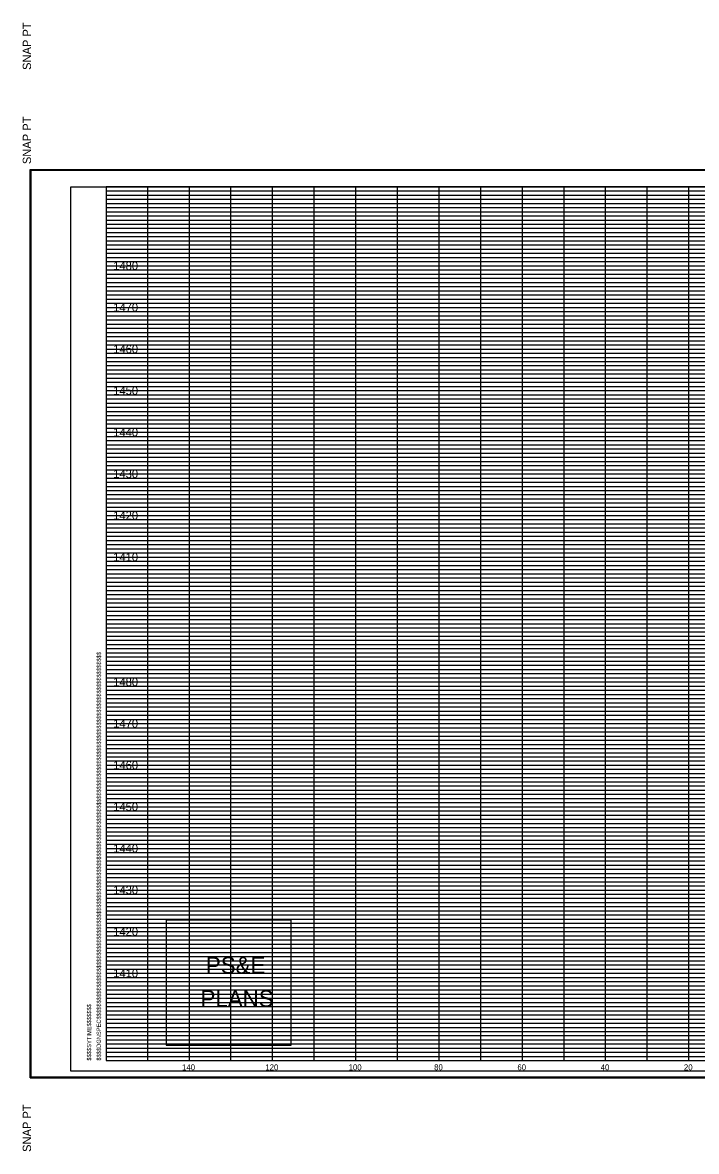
# Model space of a CAD drawing. Extents: x 980 to 2064, y 978 to 2267.
# Drawn here: x 979.9 to 1141.8, y 978.2 to 1249.4 of the extents above; entities that cross this region are included whole.
import ezdxf

# ---------------------------------------------------------------- set-up
doc = ezdxf.new("R2010")
doc.units = 0
for name, color, linetype in [('Default', 7, 'Continuous'), ('DESIGN - SHEET - Corner Text', 7, 'Continuous'), ('DESIGN - SHEET - Light Grid', 7, 'Continuous'), ('DESIGN - SHEET - Linework', 7, 'Continuous'), ('DESIGN - SHEET - Plot Shape', 7, 'Continuous')]:
    doc.layers.add(name, color=color, linetype=linetype)

# ---------------------------------------------------------------- blocks, each defined once
blk = doc.blocks.new('XSTSHT')
at = {"layer": 'DESIGN - SHEET - Light Grid'}
for p, q in [((0, 20.9), (8, 20.9)), ((8, 20.9), (16, 20.9)), ((0, 20.8), (8, 20.8)), ((0, 20.7), (8, 20.7)), ((8, 20.8), (16, 20.8)), ((8, 20.7), (16, 20.7)), ((0, 20.6), (8, 20.6)), ((0, 20.5), (8, 20.5)), ((0, 20.4), (8, 20.4)), ((8, 20.6), (16, 20.6)), ((8, 20.5), (16, 20.5)), ((8, 20.4), (16, 20.4)), ((0, 20.3), (8, 20.3)), ((0, 20.2), (8, 20.2)), ((0, 20.1), (8, 20.1)), ((8, 20.3), (16, 20.3)), ((8, 20.2), (16, 20.2)), ((8, 20.1), (16, 20.1)), ((0, 19.9), (8, 19.9)), ((8, 19.9), (16, 19.9)), ((0, 19.8), (8, 19.8)), ((0, 19.7), (8, 19.7)), ((0, 19.6), (8, 19.6)), ((8, 19.8), (16, 19.8)), ((8, 19.7), (16, 19.7)), ((8, 19.6), (16, 19.6)), ((0, 19.5), (8, 19.5)), ((0, 19.4), (8, 19.4)), ((0, 19.3), (8, 19.3)), ((8, 19.5), (16, 19.5)), ((8, 19.4), (16, 19.4)), ((8, 19.3), (16, 19.3)), ((0, 19.2), (8, 19.2)), ((0, 19.1), (8, 19.1)), ((8, 19.2), (16, 19.2)), ((8, 19.1), (16, 19.1)), ((0, 18.9), (8, 18.9)), ((0, 18.8), (8, 18.8)), ((8, 18.9), (16, 18.9)), ((8, 18.8), (16, 18.8)), ((0, 18.7), (8, 18.7)), ((0, 18.6), (8, 18.6)), ((0, 18.5), (8, 18.5)), ((8, 18.7), (16, 18.7)), ((8, 18.6), (16, 18.6)), ((8, 18.5), (16, 18.5)), ((0, 18.4), (8, 18.4)), ((0, 18.3), (8, 18.3)), ((0, 18.2), (8, 18.2)), ((8, 18.4), (16, 18.4)), ((8, 18.3), (16, 18.3)), ((8, 18.2), (16, 18.2)), ((0, 18.1), (8, 18.1)), ((8, 18.1), (16, 18.1)), ((0, 17.9), (8, 17.9)), ((0, 17.8), (8, 17.8)), ((0, 17.7), (8, 17.7)), ((8, 17.9), (16, 17.9)), ((8, 17.8), (16, 17.8)), ((8, 17.7), (16, 17.7)), ((0, 17.6), (8, 17.6)), ((0, 17.5), (8, 17.5)), ((0, 17.4), (8, 17.4)), ((8, 17.6), (16, 17.6)), ((8, 17.5), (16, 17.5)), ((8, 17.4), (16, 17.4)), ((0, 17.3), (8, 17.3)), ((0, 17.2), (8, 17.2)), ((0, 17.1), (8, 17.1)), ((8, 17.3), (16, 17.3)), ((8, 17.2), (16, 17.2)), ((8, 17.1), (16, 17.1)), ((0, 16.9), (8, 16.9)), ((8, 16.9), (16, 16.9)), ((0, 16.8), (8, 16.8)), ((0, 16.7), (8, 16.7)), ((0, 16.6), (8, 16.6)), ((8, 16.8), (16, 16.8)), ((8, 16.7), (16, 16.7)), ((8, 16.6), (16, 16.6)), ((0, 16.5), (8, 16.5)), ((0, 16.4), (8, 16.4)), ((0, 16.3), (8, 16.3)), ((8, 16.5), (16, 16.5)), ((8, 16.4), (16, 16.4)), ((8, 16.3), (16, 16.3)), ((0, 16.2), (8, 16.2)), ((0, 16.1), (8, 16.1)), ((8, 16.2), (16, 16.2)), ((8, 16.1), (16, 16.1)), ((0, 15.9), (8, 15.9)), ((0, 15.8), (8, 15.8)), ((8, 15.9), (16, 15.9)), ((8, 15.8), (16, 15.8)), ((0, 15.7), (8, 15.7)), ((0, 15.6), (8, 15.6)), ((0, 15.5), (8, 15.5)), ((8, 15.7), (16, 15.7)), ((8, 15.6), (16, 15.6)), ((8, 15.5), (16, 15.5)), ((0, 15.4), (8, 15.4)), ((0, 15.3), (8, 15.3)), ((0, 15.2), (8, 15.2)), ((8, 15.4), (16, 15.4)), ((8, 15.3), (16, 15.3)), ((8, 15.2), (16, 15.2)), ((0, 15.1), (8, 15.1)), ((8, 15.1), (16, 15.1)), ((0, 14.9), (8, 14.9)), ((0, 14.8), (8, 14.8)), ((0, 14.7), (8, 14.7)), ((8, 14.9), (16, 14.9)), ((8, 14.8), (16, 14.8)), ((8, 14.7), (16, 14.7)), ((0, 14.6), (8, 14.6)), ((0, 14.5), (8, 14.5)), ((0, 14.4), (8, 14.4)), ((8, 14.6), (16, 14.6)), ((8, 14.5), (16, 14.5)), ((8, 14.4), (16, 14.4)), ((0, 14.3), (8, 14.3)), ((0, 14.2), (8, 14.2)), ((8, 14.3), (16, 14.3)), ((8, 14.2), (16, 14.2)), ((0, 14.1), (8, 14.1)), ((0, 13.9), (8, 13.9)), ((8, 14.1), (16, 14.1)), ((8, 13.9), (16, 13.9)), ((0, 13.8), (8, 13.8)), ((0, 13.7), (8, 13.7)), ((0, 13.6), (8, 13.6)), ((8, 13.8), (16, 13.8)), ((8, 13.7), (16, 13.7)), ((8, 13.6), (16, 13.6)), ((0, 13.5), (8, 13.5)), ((0, 13.4), (8, 13.4)), ((0, 13.3), (8, 13.3)), ((8, 13.5), (16, 13.5)), ((8, 13.4), (16, 13.4)), ((8, 13.3), (16, 13.3)), ((0, 13.2), (8, 13.2)), ((0, 13.1), (8, 13.1)), ((8, 13.2), (16, 13.2)), ((8, 13.1), (16, 13.1)), ((0, 12.9), (8, 12.9)), ((0, 12.8), (8, 12.8)), ((8, 12.9), (16, 12.9)), ((8, 12.8), (16, 12.8)), ((0, 12.7), (8, 12.7)), ((0, 12.6), (8, 12.6)), ((0, 12.5), (8, 12.5)), ((8, 12.7), (16, 12.7)), ((8, 12.6), (16, 12.6)), ((8, 12.5), (16, 12.5)), ((0, 12.4), (8, 12.4)), ((0, 12.3), (8, 12.3)), ((8, 12.4), (16, 12.4)), ((8, 12.3), (16, 12.3)), ((0, 12.2), (8, 12.2)), ((0, 12.1), (8, 12.1)), ((8, 12.2), (16, 12.2)), ((8, 12.1), (16, 12.1)), ((0, 11.9), (8, 11.9)), ((0, 11.8), (8, 11.8)), ((0, 11.7), (8, 11.7)), ((8, 11.9), (16, 11.9)), ((8, 11.8), (16, 11.8)), ((8, 11.7), (16, 11.7)), ((0, 11.6), (8, 11.6)), ((0, 11.5), (8, 11.5)), ((0, 11.4), (8, 11.4)), ((8, 11.6), (16, 11.6)), ((8, 11.5), (16, 11.5)), ((8, 11.4), (16, 11.4)), ((0, 11.3), (8, 11.3)), ((0, 11.2), (8, 11.2)), ((8, 11.3), (16, 11.3)), ((8, 11.2), (16, 11.2)), ((0, 11.1), (8, 11.1)), ((0, 10.9), (8, 10.9)), ((8, 11.1), (16, 11.1)), ((8, 10.9), (16, 10.9)), ((0, 10.8), (8, 10.8)), ((0, 10.7), (8, 10.7)), ((0, 10.6), (8, 10.6)), ((8, 10.8), (16, 10.8)), ((8, 10.7), (16, 10.7)), ((8, 10.6), (16, 10.6)), ((0, 10.5), (8, 10.5)), ((0, 10.4), (8, 10.4)), ((8, 10.5), (16, 10.5)), ((8, 10.4), (16, 10.4)), ((0, 10.3), (8, 10.3)), ((0, 10.2), (8, 10.2)), ((0, 10.1), (8, 10.1)), ((8, 10.3), (16, 10.3)), ((8, 10.2), (16, 10.2)), ((8, 10.1), (16, 10.1)), ((0, 9.9), (8, 9.9)), ((0, 9.8), (8, 9.8)), ((8, 9.9), (16, 9.9)), ((8, 9.8), (16, 9.8)), ((0, 9.7), (8, 9.7)), ((0, 9.6), (8, 9.6)), ((0, 9.5), (8, 9.5)), ((8, 9.7), (16, 9.7)), ((8, 9.6), (16, 9.6)), ((8, 9.5), (16, 9.5)), ((0, 9.4), (8, 9.4)), ((0, 9.3), (8, 9.3)), ((8, 9.4), (16, 9.4)), ((8, 9.3), (16, 9.3)), ((0, 9.2), (8, 9.2)), ((0, 9.1), (8, 9.1)), ((8, 9.2), (16, 9.2)), ((8, 9.1), (16, 9.1)), ((0, 8.9), (8, 8.9)), ((0, 8.8), (8, 8.8)), ((0, 8.7), (8, 8.7)), ((8, 8.9), (16, 8.9)), ((8, 8.8), (16, 8.8)), ((8, 8.7), (16, 8.7)), ((0, 8.6), (8, 8.6)), ((0, 8.5), (8, 8.5)), ((8, 8.6), (16, 8.6)), ((8, 8.5), (16, 8.5)), ((0, 8.4), (8, 8.4)), ((0, 8.3), (8, 8.3)), ((0, 8.2), (8, 8.2)), ((8, 8.4), (16, 8.4)), ((8, 8.3), (16, 8.3)), ((8, 8.2), (16, 8.2)), ((0, 8.1), (8, 8.1)), ((0, 7.9), (8, 7.9)), ((8, 8.1), (16, 8.1)), ((8, 7.9), (16, 7.9)), ((0, 7.8), (8, 7.8)), ((0, 7.7), (8, 7.7)), ((0, 7.6), (8, 7.6)), ((8, 7.8), (16, 7.8)), ((8, 7.7), (16, 7.7)), ((8, 7.6), (16, 7.6)), ((0, 7.5), (8, 7.5)), ((0, 7.4), (8, 7.4)), ((8, 7.5), (16, 7.5)), ((8, 7.4), (16, 7.4)), ((0, 7.3), (8, 7.3)), ((0, 7.2), (8, 7.2)), ((0, 7.1), (8, 7.1)), ((8, 7.3), (16, 7.3)), ((8, 7.2), (16, 7.2)), ((8, 7.1), (16, 7.1)), ((0, 6.9), (8, 6.9)), ((0, 6.8), (8, 6.8)), ((8, 6.9), (16, 6.9)), ((8, 6.8), (16, 6.8)), ((0, 6.7), (8, 6.7)), ((0, 6.6), (8, 6.6)), ((8, 6.7), (16, 6.7)), ((8, 6.6), (16, 6.6)), ((0, 6.5), (8, 6.5)), ((0, 6.4), (8, 6.4)), ((0, 6.3), (8, 6.3)), ((8, 6.5), (16, 6.5)), ((8, 6.4), (16, 6.4)), ((8, 6.3), (16, 6.3)), ((0, 6.2), (8, 6.2)), ((0, 6.1), (8, 6.1)), ((8, 6.2), (16, 6.2)), ((8, 6.1), (16, 6.1)), ((0, 5.9), (8, 5.9)), ((0, 5.8), (8, 5.8)), ((0, 5.7), (8, 5.7)), ((8, 5.9), (16, 5.9)), ((8, 5.8), (16, 5.8)), ((8, 5.7), (16, 5.7)), ((0, 5.6), (8, 5.6)), ((0, 5.5), (8, 5.5)), ((8, 5.6), (16, 5.6)), ((8, 5.5), (16, 5.5)), ((0, 5.4), (8, 5.4)), ((0, 5.3), (8, 5.3)), ((0, 5.2), (8, 5.2)), ((8, 5.4), (16, 5.4)), ((8, 5.3), (16, 5.3)), ((8, 5.2), (16, 5.2)), ((0, 5.1), (8, 5.1)), ((0, 4.9), (8, 4.9)), ((8, 5.1), (16, 5.1)), ((8, 4.9), (16, 4.9)), ((0, 4.8), (8, 4.8)), ((0, 4.7), (8, 4.7)), ((8, 4.8), (16, 4.8)), ((8, 4.7), (16, 4.7)), ((0, 4.6), (8, 4.6)), ((0, 4.5), (8, 4.5)), ((0, 4.4), (8, 4.4)), ((8, 4.6), (16, 4.6)), ((8, 4.5), (16, 4.5)), ((8, 4.4), (16, 4.4)), ((0, 4.3), (8, 4.3)), ((0, 4.2), (8, 4.2)), ((0, 4.1), (8, 4.1)), ((8, 4.3), (16, 4.3)), ((8, 4.2), (16, 4.2)), ((8, 4.1), (16, 4.1)), ((0, 3.9), (8, 3.9)), ((0, 3.8), (8, 3.8)), ((8, 3.9), (16, 3.9)), ((8, 3.8), (16, 3.8)), ((0, 3.7), (8, 3.7)), ((0, 3.6), (8, 3.6)), ((8, 3.7), (16, 3.7)), ((8, 3.6), (16, 3.6)), ((0, 3.5), (8, 3.5)), ((0, 3.4), (8, 3.4)), ((0, 3.3), (8, 3.3)), ((8, 3.5), (16, 3.5)), ((8, 3.4), (16, 3.4)), ((8, 3.3), (16, 3.3)), ((0, 3.2), (8, 3.2)), ((0, 3.1), (8, 3.1)), ((8, 3.2), (16, 3.2)), ((8, 3.1), (16, 3.1)), ((0, 2.9), (8, 2.9)), ((0, 2.8), (8, 2.8)), ((8, 2.9), (16, 2.9)), ((8, 2.8), (16, 2.8)), ((0, 2.7), (8, 2.7)), ((0, 2.6), (8, 2.6)), ((0, 2.5), (8, 2.5)), ((8, 2.7), (16, 2.7)), ((8, 2.6), (16, 2.6)), ((8, 2.5), (16, 2.5)), ((0, 2.4), (8, 2.4)), ((0, 2.3), (8, 2.3)), ((0, 2.2), (8, 2.2)), ((8, 2.4), (16, 2.4)), ((8, 2.3), (16, 2.3)), ((8, 2.2), (16, 2.2)), ((0, 2.1), (8, 2.1)), ((0, 1.9), (8, 1.9)), ((8, 2.1), (16, 2.1)), ((8, 1.9), (16, 1.9)), ((0, 1.8), (8, 1.8)), ((0, 1.7), (8, 1.7)), ((8, 1.8), (16, 1.8)), ((8, 1.7), (16, 1.7)), ((0, 1.6), (8, 1.6)), ((0, 1.5), (8, 1.5)), ((0, 1.4), (8, 1.4)), ((8, 1.6), (16, 1.6)), ((8, 1.5), (16, 1.5)), ((8, 1.4), (16, 1.4)), ((0, 1.3), (8, 1.3)), ((0, 1.2), (8, 1.2)), ((0, 1.1), (8, 1.1)), ((8, 1.3), (16, 1.3)), ((8, 1.2), (16, 1.2)), ((8, 1.1), (16, 1.1)), ((0, 0.9), (8, 0.9)), ((8, 0.9), (16, 0.9)), ((0, 0.8), (8, 0.8)), ((0, 0.7), (8, 0.7)), ((0, 0.6), (8, 0.6)), ((8, 0.8), (16, 0.8)), ((8, 0.7), (16, 0.7)), ((8, 0.6), (16, 0.6)), ((0, 0.5), (8, 0.5)), ((0, 0.4), (8, 0.4)), ((0, 0.3), (8, 0.3)), ((8, 0.5), (16, 0.5)), ((8, 0.4), (16, 0.4)), ((8, 0.3), (16, 0.3)), ((0, 0.2), (8, 0.2)), ((0, 0.1), (8, 0.1)), ((8, 0.2), (16, 0.2)), ((8, 0.1), (16, 0.1))]:
    blk.add_line(p, q, dxfattribs=at)
at = {"layer": 'DESIGN - SHEET - Linework'}
for p, q in [((-1.823, -0.414), (-1.823, 21.414)), ((-1.823, 21.414), (32.217, 21.414)), ((1, 0), (1, 21)), ((2, 0), (2, 21)), ((3, 0), (3, 21)), ((4, 0), (4, 21)), ((5, 0), (5, 21)), ((6, 0), (6, 21)), ((7, 0), (7, 21)), ((8, 0), (8, 21)), ((9, 0), (9, 21)), ((10, 0), (10, 21)), ((11, 0), (11, 21)), ((12, 0), (12, 21)), ((13, 0), (13, 21)), ((14, 0), (14, 21)), ((0, 20), (28, 20)), ((0, 19), (32, 19)), ((0, 18), (32, 18)), ((0, 17), (32, 17)), ((0, 16), (32, 16)), ((0, 15), (32, 15)), ((0, 14), (32, 14)), ((0, 13), (32, 13)), ((0, 12), (32, 12)), ((0, 11), (32, 11)), ((0, 10), (32, 10)), ((0, 9), (32, 9)), ((0, 8), (32, 8)), ((0, 7), (32, 7)), ((0, 6), (32, 6)), ((0, 5), (32, 5)), ((0, 4), (32, 4)), ((0, 3), (32, 3)), ((0, 2), (32, 2)), ((0, 1), (32, 1)), ((-1.823, -0.414), (32.217, -0.414))]:
    blk.add_line(p, q, dxfattribs=at)
blk.add_lwpolyline([(0, 21), (0, 0), (32, 0), (32, 21), (0, 21)], dxfattribs=at)
at = {"layer": 'DESIGN - SHEET - Plot Shape'}
for points in [[(-1.803, 21.394), (32.197, 21.394), (32.197, -0.394), (-1.803, -0.394)], [(-0.85, 21), (32, 21), (32, -0.25), (-0.85, -0.25)]]:
    blk.add_lwpolyline(points, close=True, dxfattribs=at)
at = {"layer": 'DESIGN - SHEET - Corner Text'}
for s, height, p in [('  SNAP PT', 0.2, (-1.803, 21.394)), ('$$$$DGNSPEC$$$$$$$$$$$$$$$$$$$$$$$$$$$$$$$$$$$$$$$$$$$$$$$$$$$$$$$$$$$$$$$$$$$$$$$$$$$$$$$$$$$$$$$$$$$$$$$$$$$$$$$$$$$$$$$$$$$', 0.100002, (-0.126, 0)), ('$$$$SYTIME$$$$$$$', 0.1, (-0.358, 0)), ('SNAP PT  ', 0.2, (-1.803, -2.194))]:
    blk.add_text(s, height=height, rotation=90, dxfattribs=at).set_placement(p)

msp = doc.modelspace()

# ---------------------------------------------------------------- linework, layer by layer
at = {"layer": 'DESIGN - SHEET - Corner Text'}
msp.add_lwpolyline([(1014.46, 1033.74), (1014.46, 1003.74), (1044.46, 1003.74), (1044.46, 1033.74)], close=True, dxfattribs=at)

# ---------------------------------------------------------------- block references
at = {"layer": 'Default', "xscale": 10, "yscale": 10}
msp.add_blockref('XSTSHT', (1000, 1000), dxfattribs=at)

# ---------------------------------------------------------------- texts
at = {"layer": 'Default'}
for s, height, p in [('     1480     ', 2, (998.01, 1190)), ('     1470     ', 2, (998.01, 1180)), ('     1460     ', 2, (998.01, 1170)), ('     1450     ', 2, (998.01, 1160)), ('     1440     ', 2, (998.01, 1150)), ('     1430     ', 2, (998.01, 1140)), ('     1420     ', 2, (998.01, 1130)), ('     1410     ', 2, (998.01, 1120)), ('     1480     ', 2, (998.01, 1090)), ('     1470     ', 2, (998.01, 1080)), ('     1460     ', 2, (998.01, 1070)), ('     1450     ', 2, (998.01, 1060)), ('     1440     ', 2, (998.01, 1050)), ('     1430     ', 2, (998.01, 1040)), ('     1420     ', 2, (998.01, 1030)), ('     1410     ', 2, (998.01, 1020)), ('     140     ', 1.4, (1015.65, 997.7)), ('     120     ', 1.4, (1035.65, 997.7)), ('     100     ', 1.4, (1055.65, 997.7)), ('     80     ', 1.4, (1076.2, 997.7)), ('     60     ', 1.4, (1096.2, 997.7)), ('     40     ', 1.4, (1116.2, 997.7)), ('     20     ', 1.4, (1136.2, 997.7))]:
    msp.add_text(s, height=height, dxfattribs=at).set_placement(p)
at = {"layer": 'DESIGN - SHEET - Corner Text'}
msp.add_text('SNAP PT  ', height=2, rotation=90, dxfattribs=at).set_placement((981.97, 1238.06))
for s, p in [('PS&E', (1023.98, 1020.92)), ('PLANS', (1022.69, 1012.92))]:
    msp.add_text(s, height=4, dxfattribs=at).set_placement(p)

doc.saveas('drawing.dxf')
